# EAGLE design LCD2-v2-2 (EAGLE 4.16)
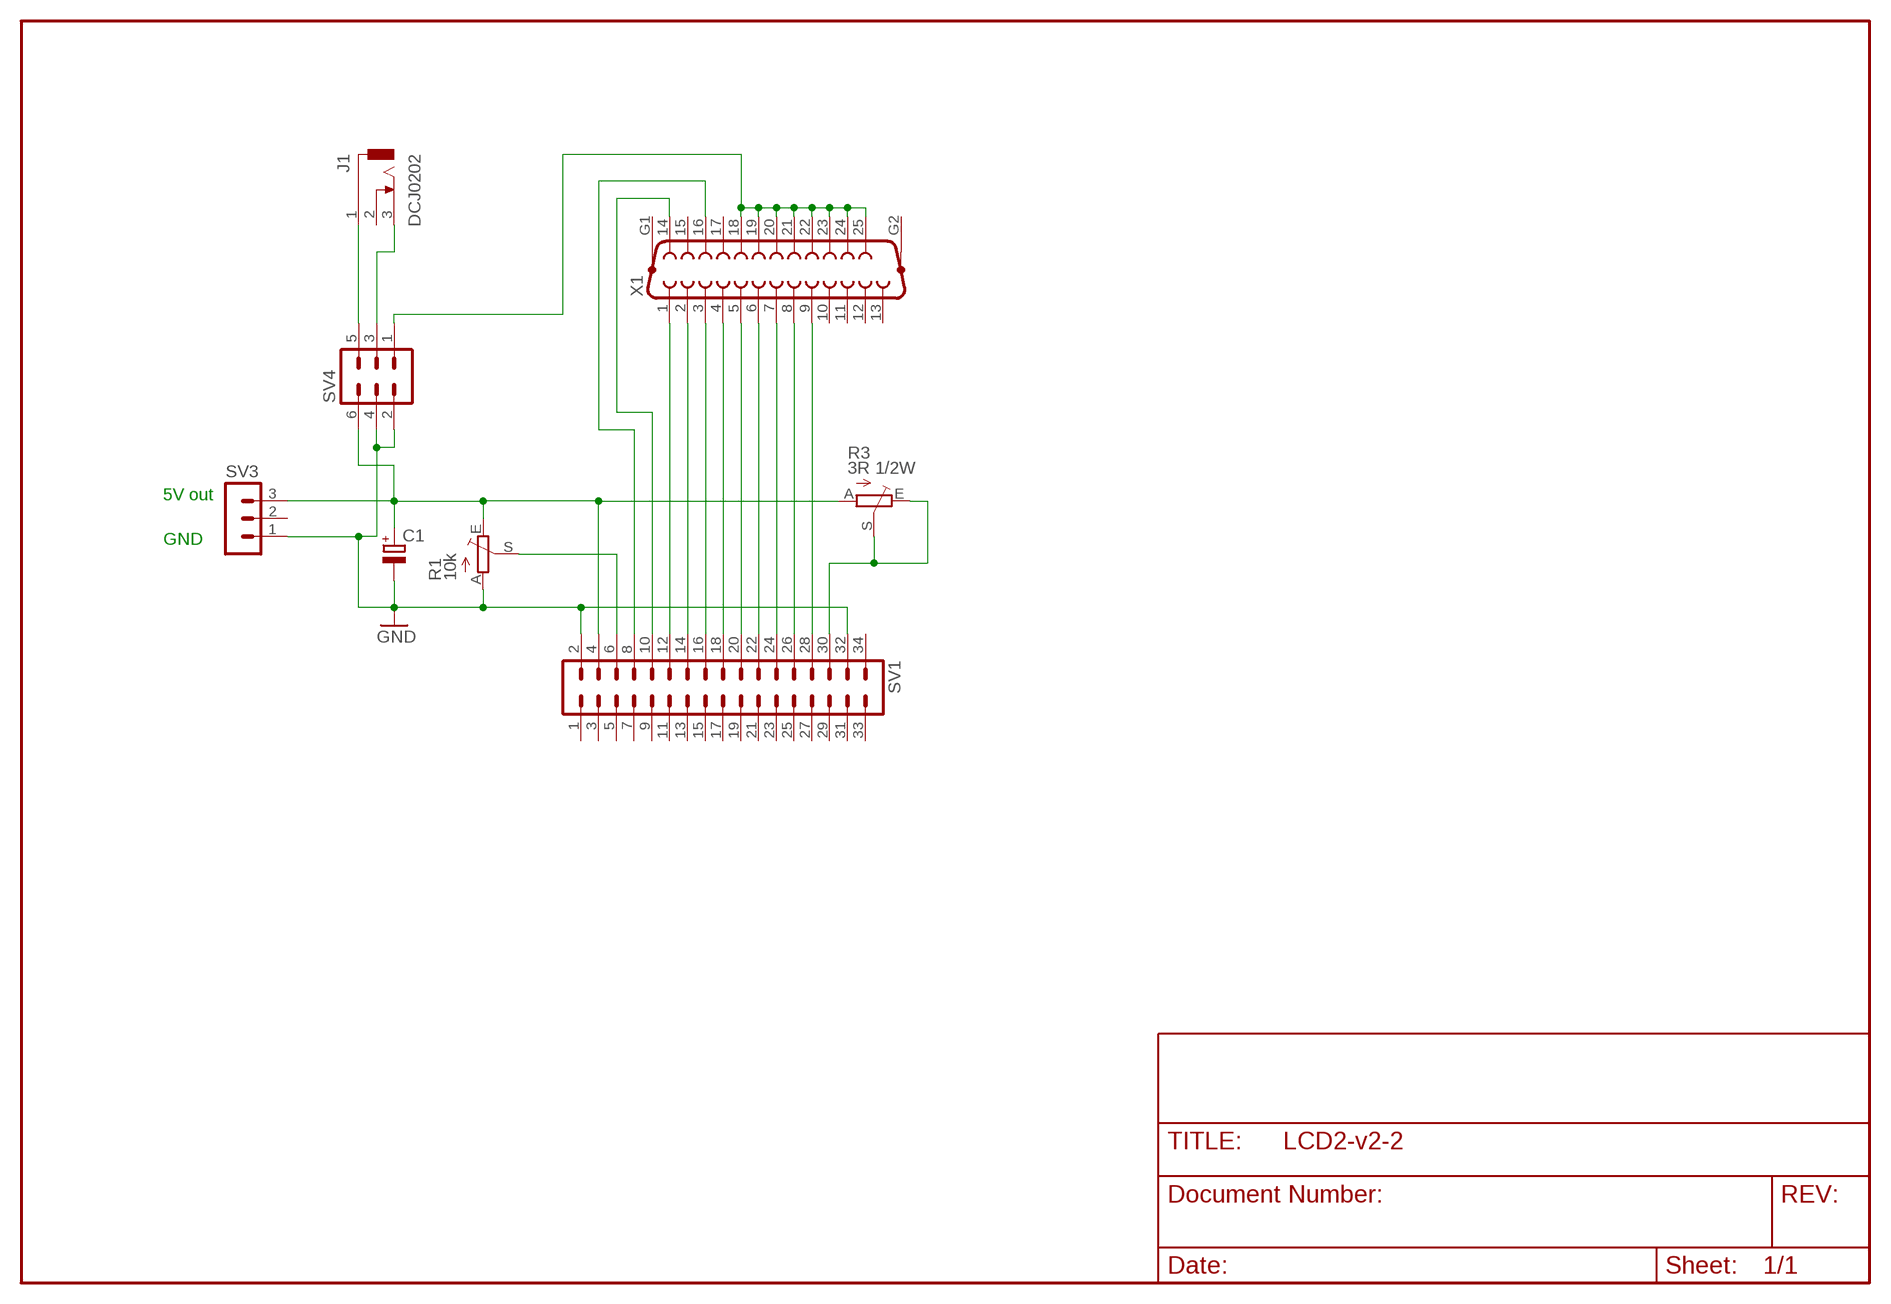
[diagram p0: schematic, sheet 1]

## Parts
C1  CPOL-EUE5-8.5  [E5-8,5]
J1  DCJ0202  [DCJ0202]
R1  10k  TRIM_EU-CA9V  [CA9V]
R3  3R 1/2W  TRIM_EU-CA9V  [CA9V]
SV1  MA17-2  [MA17-2]
SV3  MA03-1  [MA03-1]
SV4  MA03-2  [MA03-2]
X1  F25HP  [F25HP]

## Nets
GND: C1.- R1.A SV1.2 SV1.32 SV3.1 SV4.2 SV4.4
N$1: SV1.12 X1.1
N$2: SV1.14 X1.2
N$3: SV1.16 X1.3
N$4: SV1.18 X1.4
N$5: SV1.20 X1.5
N$6: SV1.22 X1.6
N$7: SV1.24 X1.7
N$8: SV1.26 X1.8
N$9: SV1.28 X1.9
N$10: SV1.10 X1.14
N$11: SV1.8 X1.16
N$12: J1.1 SV4.5
N$13: R1.S SV1.6
N$14: C1.+ R1.E R3.A SV1.4 SV3.3 SV4.6
N$15: J1.3 SV4.3
N$17: R3.E R3.S SV1.30
N$18: SV4.1 X1.18 X1.19 X1.20 X1.21 X1.22 X1.23 X1.24 X1.25
Unconnected: J1.2 SV1.1 SV1.3 SV1.5 SV1.7 SV1.9 SV1.11 SV1.13 SV1.15 SV1.17 SV1.19 SV1.21 SV1.23 SV1.25 SV1.27 SV1.29 SV1.31 SV1.33 SV1.34 SV3.2 X1.10 X1.11 X1.12 X1.13 X1.15 X1.17 X1.G1 X1.G2

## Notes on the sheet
- 5V out
- GND

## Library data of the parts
C1 = rcl:CPOL-EU: POLARIZED CAPACITOR, European symbol
J1 = con-jack:DCJ0202: DC POWER JACK Source: DCJ0202.pdf
R1 R3 = pot:TRIM_EU-: POTENTIOMETER
SV1 = con-lstb:MA17-2: PIN HEADER
SV3 = con-lstb:MA03-1: PIN HEADER
SV4 = con-lstb:MA03-2: PIN HEADER
X1 = con-subd:F25HP: SUB-D

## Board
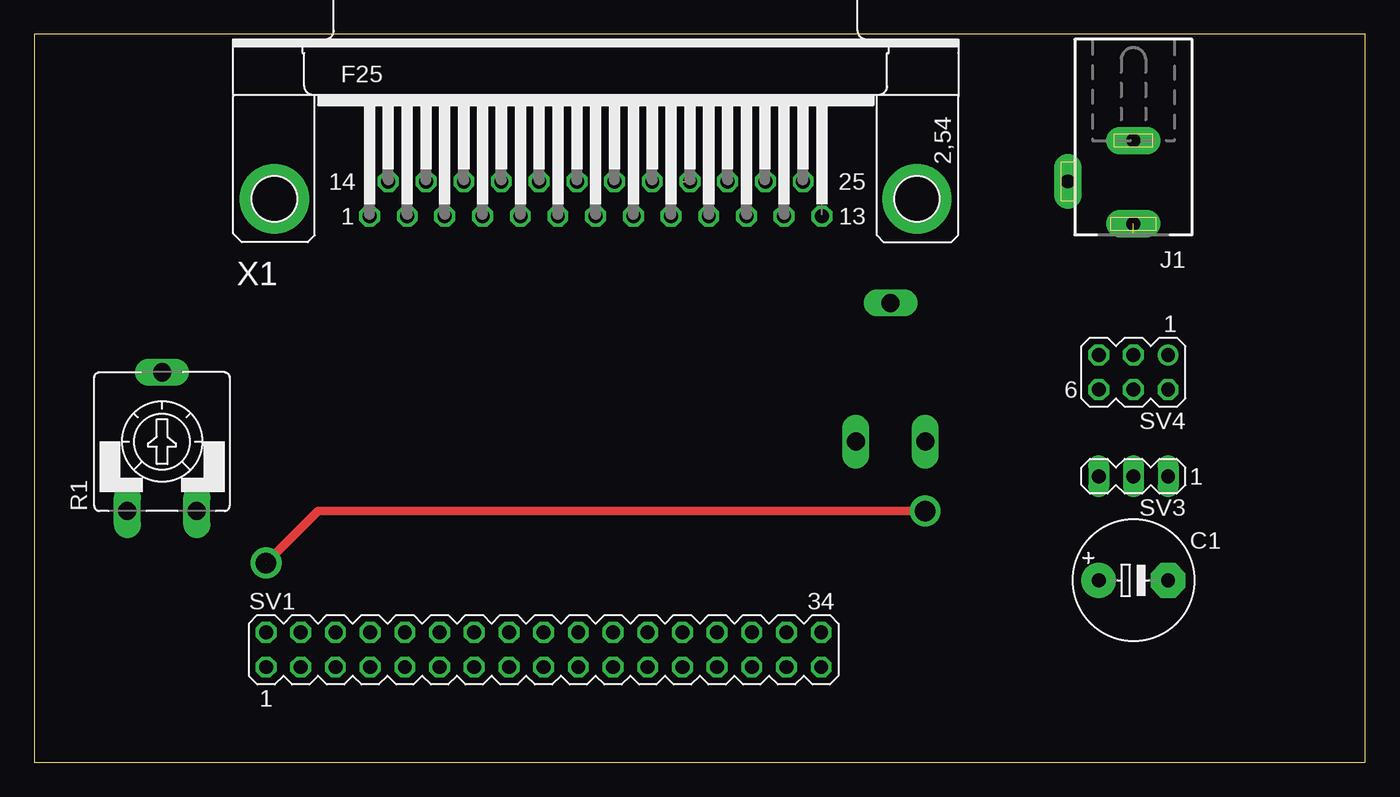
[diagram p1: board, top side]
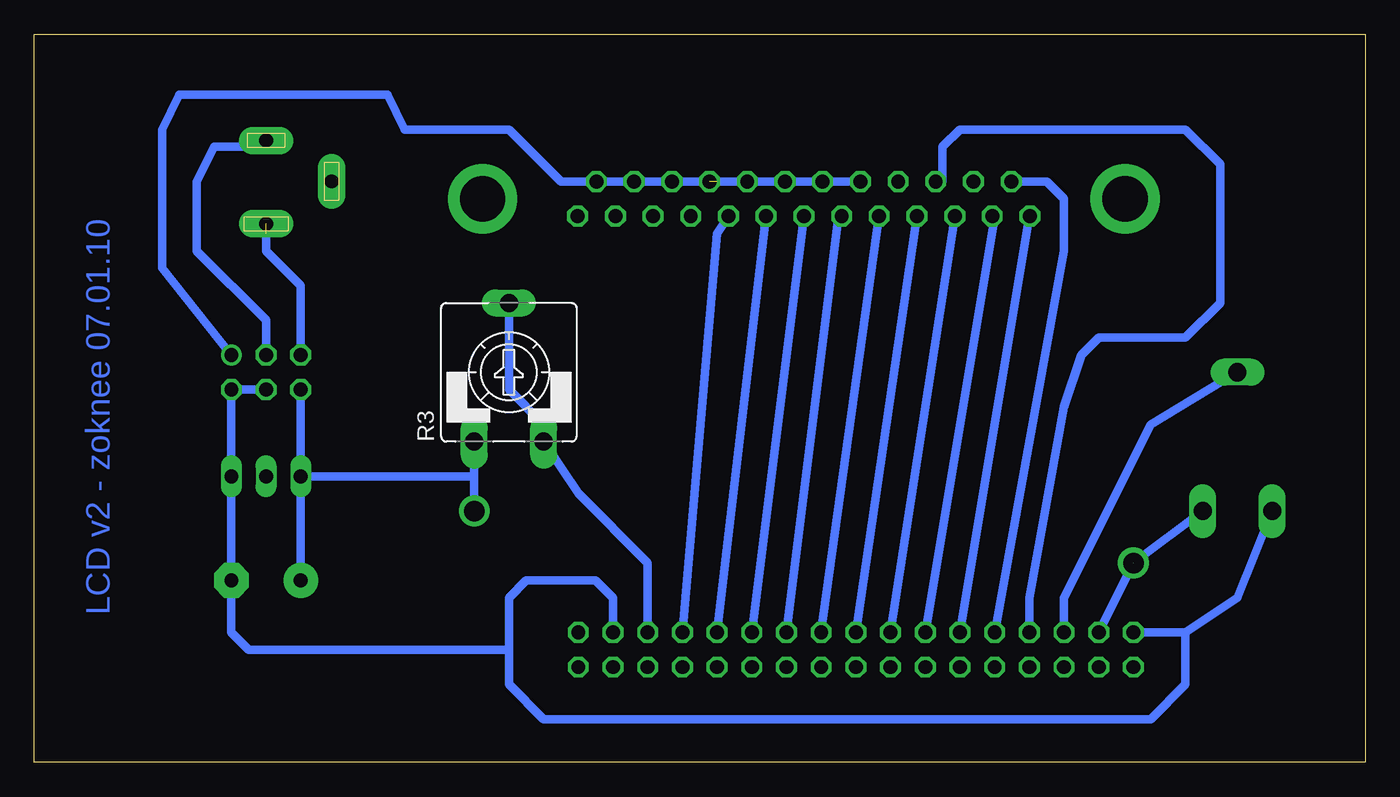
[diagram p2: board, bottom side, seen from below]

Size 97.46 x 53.33 mm. Coordinates in mm from the lower left corner, seen from the top.
Outline: 0,0 97.46,0 97.46,53.33 0,53.33 0,0
Copper layers 1*16: Top 0.035mm / dielectric 1.5mm / Bottom 0.035mm
Design rules "1retegu": minimum track width 20mil, minimum drill 24mil, track to track 10mil, track to pad 10mil, pad to pad 8mil, via to via 8mil, smd to smd 8mil, copper to edge 40mil, drill to drill 8mil, minimum pad ring 10mil, minimum via ring 8mil, stop-mask expansion 4mil, vias tented up to drill 0mil, thermal gap 10mil

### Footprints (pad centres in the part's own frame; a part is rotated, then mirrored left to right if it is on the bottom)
E5-8,5 = drill 1.016 pad 2.54 round: + -2.54,0 | drill 1.016 pad 2.54 octagon: - 2.54,0
DCJ0202 = drill 1 pad 2 long: 1 0,3.1; 2 4.8,0; 3 0,-3
CA9V = drill 1.321 long: A -2.54,-5.08; E 2.54,-5.08; S 0,5.08
MA17-2 = drill 1.016 octagon: 1 -20.32,-1.27; 2 -20.32,1.27; 3 -17.78,-1.27; 4 -17.78,1.27; 5 -15.24,-1.27; 6 -15.24,1.27; 7 -12.7,-1.27; 8 -12.7,1.27; 9 -10.16,-1.27; 10 -10.16,1.27; 11 -7.62,-1.27; 12 -7.62,1.27; 13 -5.08,-1.27; 14 -5.08,1.27; 15 -2.54,-1.27; 16 -2.54,1.27; 17 0,-1.27; 18 0,1.27; 19 2.54,-1.27; 20 2.54,1.27; 21 5.08,-1.27; 22 5.08,1.27; 23 7.62,-1.27; 24 7.62,1.27; 25 10.16,-1.27; 26 10.16,1.27; 27 12.7,-1.27; 28 12.7,1.27; 29 15.24,-1.27; 30 15.24,1.27; 31 17.78,-1.27; 32 17.78,1.27; 33 20.32,-1.27; 34 20.32,1.27
MA03-1 = drill 1.016 long: 1 -2.54,0; 2 0,0; 3 2.54,0
MA03-2 = drill 1.016 round: 1 -2.54,-1.27 | drill 1.016 octagon: 2 -2.54,1.27; 3 0,-1.27; 4 0,1.27; 5 2.54,-1.27; 6 2.54,1.27
F25HP = drill 1.016 octagon: 1 -16.561,-1.27; 2 -13.792,-1.27; 3 -11.049,-1.27; 4 -8.28,-1.27; 5 -5.512,-1.27; 6 -2.769,-1.27; 7 0,-1.27; 8 2.769,-1.27; 9 5.512,-1.27; 10 8.28,-1.27; 11 11.049,-1.27; 12 13.792,-1.27; 13 16.561,-1.27; 14 -15.189,1.27; 15 -12.421,1.27; 16 -9.652,1.27; 17 -6.909,1.27; 18 -4.14,1.27; 19 -1.372,1.27; 20 1.372,1.27; 21 4.14,1.27; 22 6.909,1.27; 23 9.652,1.27; 24 12.421,1.27; 25 15.189,1.27 | drill 3.302 pad 5.08 round: G1 -23.52,0; G2 23.52,0

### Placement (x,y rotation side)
C1  80.48,13.33 0 top
J1  80.48,42.54 180 top
R1  9.36,23.49 0 top
R3  62.7,28.57 0 bottom
SV1  37.3,8.25 0 top
SV3  80.48,20.95 180 top
SV4  80.48,28.57 180 top
X1  41.11,41.27 0 top

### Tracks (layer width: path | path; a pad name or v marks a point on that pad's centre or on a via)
GND
  Bottom 0.61: SV4.4 SV4.2 SV3.1 C1.- 83.02,9.52 81.75,8.25 62.7,8.25 | 13.17,9.52 9.36,12.06 R1.A | 13.17,9.52 SV1.2 | 13.17,9.52 13.17,5.71 15.71,3.17 60.16,3.17 62.7,5.71 62.7,8.25 | SV1.32 55.08,12.06 56.35,13.33 61.43,13.33 62.7,12.06 62.7,8.25
N$1
  Bottom 0.61: X1.1 24.6,40 SV1.12
N$2
  Bottom 0.61: X1.2 27.14,40 SV1.14
N$3
  Bottom 0.61: SV1.16 X1.3
N$4
  Bottom 0.61: SV1.18 X1.4
N$5
  Bottom 0.61: SV1.20 X1.5
N$6
  Bottom 0.61: X1.6 38.57,40 SV1.22
N$7
  Bottom 0.61: SV1.24 X1.7
N$8
  Bottom 0.61: SV1.26 X1.8
N$9
  Bottom 0.61: SV1.28 47.46,38.73 X1.9 46.19,40
N$10
  Bottom 0.61: X1.14 23.33,42.54 22.06,41.27 22.06,37.46 SV1.10
N$11
  Bottom 0.61: X1.16 30.95,42.54 30.95,45.08 29.68,46.35 13.17,46.35 10.63,43.81 10.63,33.65 13.17,31.11 19.52,31.11 20.79,29.84 22.06,26.03 24.6,12.06 SV1.8
N$12  (1 unrouted)
  Bottom 0.61: SV4.5 77.94,34.92 80.48,37.46 80.48,38.73
N$13
  Bottom 0.61: SV1.6 22.06,12.06 15.71,24.76 R1.S
N$14  (via drill 1.5)  (1 unrouted)
  Top 0.61: v65.24,18.41 20.79,18.41 16.98,14.6
  Bottom 0.61: SV3.3 SV4.6 | SV3.3 C1.+ | 65.24,20.95 R3.A | 65.24,20.95 SV3.3 | R1.E 16.98,14.6 SV1.4 | v65.24,18.41 65.24,20.95
N$15
  Bottom 0.61: SV4.3 80.48,32.38 85.56,37.46 85.56,42.54 84.29,45.08 80.48,45.08 J1.3
N$16  (via drill 1.5)
  other vias: 16.98,14.6
N$17
  Bottom 0.61: R3.S 62.7,27.3 60.16,24.76 R3.E 57.62,19.68 52.54,14.6 SV1.30
N$18  (1 unrouted)
  Bottom 0.61: X1.19 39.84,42.54 | X1.18 X1.19 | X1.19 X1.20 X1.21 47.46,42.54 | X1.22 X1.23 X1.24 | X1.24 53.81,42.54 | X1.25 56.35,42.54 | X1.24 X1.25 | X1.25 58.89,42.54 62.7,46.35 70.32,46.35 71.59,48.89 86.83,48.89 88.1,46.35 88.1,36.19 SV4.1

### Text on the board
Bottom: LCD v2 - zoknee 07.01.10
